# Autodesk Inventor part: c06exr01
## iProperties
Shininess: 77.0
Length Units: 11269
Angle Units: 11279
Time Units: 11290
Mass Units: 11283
Length Display Precision: 3
Angle Display Precision: 2
Created: 2001-12
Part Number: c06exr01
Document SubType Name: Modeling
Density: 1 g/cm^3
Density: 0.0
Volumn: 0.0
Area: 0.0
PropertySet Name: Model Information
Control State: 0
Master: False
Checked Out: False
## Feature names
1. Extrusion1
2. Extrusion2
3. Extrusion3
4. Extrusion4
5. Extrusion5
6. Extrusion6
7. Hole1
